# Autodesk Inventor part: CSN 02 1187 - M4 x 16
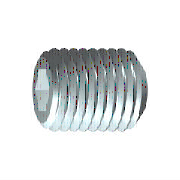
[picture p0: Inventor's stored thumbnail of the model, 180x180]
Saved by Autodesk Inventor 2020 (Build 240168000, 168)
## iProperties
Created: 2019-01
Part Number: CSN 02 1187 - M4 x 16
Material: Ocel, měkká
Description: Stavěcí šroub s vnitřním šestihranem s plochým kuželovým koncem
Document SubType Name: Modeling
Standard: CSN 02 1187
Designer: doma
Standards Organization: CSN
Language: cs-CZ
Size Designation: M4 x 16
Categories: <MemberInstance><Categories><Category DisplayName="Spojovací materiál" InternalName="e4da775c-781d-43d5-af7c-5136215cf5a6" Mnemonic="FSTN"><Category DisplayName
Density: 7.85 g/cm^3
Appearance: Pololeštěná
IsCustomPart: 0
Author: doma
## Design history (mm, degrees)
sketch "Náčrt1"
  geometry: L1 (0, 0)-(12.833, 0); L2 (16, 1.155)-(16, 2); L3 (16, 2)-(0, 2); L4 (16, 1.155)-(13.5, 1.155); L5 (13.5, 1.155)-(12.833, 0); L6 (0, -0.4)-(0, 2.4) reference; L7 (0, 2)-(0, 0)
  constraints: 13 end point, 3 parallel, 1 collinear, 1 perpendicular, 1 point on line
  dimensions: "d0" = 2.5 distance of L2.start L4.end (= INTI); "d1" = 60 deg angle of L5 L1; "d2" = 4 diameter of L3 L1 (= NND); "d3" = 2.3094 diameter of L4 L1 (= 1.1547 x SW); "d5" = 16 distance from line of L2 L3.end (= NLG)
revolve "Těleso" sketch "Náčrt1" stored, may be unused: angle "d6" = 90 deg
sketch "Náčrt2"
  geometry: L1 (-0.577, 1)-(0.577, 1); L2 (0.577, 1)-(1.155, 0); L3 (1.155, 0)-(0.577, -1); L4 (0.577, -1)-(-0.577, -1); L5 (-0.577, -1)-(-1.155, 0); L6 (-1.155, 0)-(-0.577, 1); A1 r 1.155 centre (0, 0) between (-0.577, 1) and (0.577, 1) reference; 2 further points
  constraints: 12 end point, 2 point on circle, 1 coincident, 1 horizontal, 11 other
extrude "Drážka" join sketch "Náčrt2" taper "d9" = 0 deg; stored distance "d21" = 10
workaxis "Work Axis1"
workplane "Work Plane1"
body "Solid1"
chamfer "Zkosení1" distance "d7" = 0.42941 (= -0.5 x GD1 + 0.5 x NND); stored, may be unused: angle "d8" = 60 deg (= FAWI), second distance "d29" = 0.42941 (= -0.5 x GD1 + 0.5 x NND)
feature "Závit" dims "d11" = 16 (= NLG), "d12" = 0
chamfer "Zkosení2" distance "d13" = 0.42941 (= -0.5 x GD1 + 0.5 x NND); stored, may be unused: angle "d14" = 60 deg (= FAWI), second distance "d30" = 0.42941 (= -0.5 x GD1 + 0.5 x NND)
other parameters: "NND" = 4 [user parameter; used in 6 equation terms], "NLG" = 16 [user parameter; used in 2 equation terms], "INTI" = 2.5 [user parameter; used in 1 equation term], "FAWI" = 60 deg [user parameter; used in 2 equation terms], "SW" = 2 [user parameter; used in 2 equation terms], "GD1" = 3.14117 (= THREADDIA - 1.2269 x PTC) [user parameter; used in 4 equation terms], "d4" = 0, "FAWI1" = 30 deg [user parameter], "d15" = 0, "d31" = 0, "GUL" = 0.42941 (= 0.61345 x PTC) [user parameter], "SPD" = 3.14117 (= NND - 1.2269 x PTC) [user parameter], "TPU" = 14.28571 (computed from PTC) [user parameter], "TOA" = 30 deg [user parameter], "THREADDIA" = 4 [user parameter; used in 1 equation term], "PTC" = 0.7 [user parameter; used in 5 equation terms], "GAL" = 0.42941 (= 0.61345 x PTC) [user parameter], "E0" = 2.31 (= 1.155 x SW) [user parameter]
